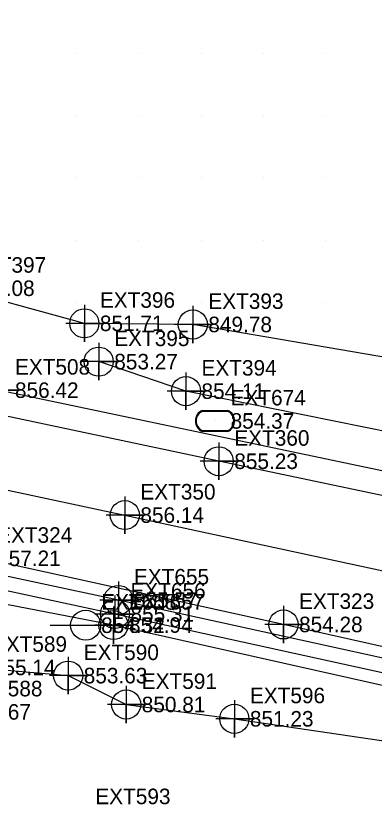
# Model space of a CAD drawing. Extents: x 1762120 to 1766775, y 709485 to 712965.
# Drawn here: x 1762750.2 to 1762807.8, y 712600.2 to 712726.1 of the extents above; entities that cross this region are included whole.
import ezdxf

# ---------------------------------------------------------------- set-up
doc = ezdxf.new("R2010")
doc.units = 0
for name, color, linetype in [('Exist DTM Breakline', 7, 'Continuous'), ('Exist DTM Breakline Cogo Elevation', 7, 'Continuous'), ('Exist DTM Breakline Cogo Number', 7, 'Continuous'), ('Exist DTM Breakline Cogo Point CELL', 7, 'Continuous'), ('Exist DTM Crownline', 7, 'Continuous'), ('Exist DTM Crownline Cogo Elevation', 7, 'Continuous'), ('Exist DTM Crownline Cogo Number', 7, 'Continuous'), ('Exist DTM Crownline Cogo Point CELL', 7, 'Continuous'), ('Exist DTM Drainline', 7, 'Continuous'), ('Exist DTM Drainline Cogo Elevation', 7, 'Continuous'), ('Exist DTM Drainline Cogo Number', 7, 'Continuous'), ('Exist DTM Drainline Cogo Point CELL', 7, 'Continuous'), ('Exist DTM QL2 LIDAR Elevation Point', 7, 'Continuous'), ('Exist Roads EOP', 7, 'Continuous'), ('Exist Roads EOP Cogo Elevation', 7, 'Continuous'), ('Exist Roads EOP Cogo Number', 7, 'Continuous'), ('Exist Roads EOP Cogo Point CELL', 7, 'Continuous'), ('Exist Utilities Gas UG Line SUE LOS C', 7, 'Continuous'), ('Exist Utilities Gas UG Line SUE LOS C Cogo Elevation', 7, 'Continuous'), ('Exist Utilities Gas UG Line SUE LOS C Cogo Number', 7, 'Continuous'), ('Exist Utilities Gas UG Line SUE LOS C Cogo Point CELL', 7, 'Continuous'), ('Exist Utilities Telephone Pole CELL', 7, 'Continuous'), ('Exist Utilities Telephone Pole Cogo Elevation', 7, 'Continuous'), ('Exist Utilities Telephone Pole Cogo Number', 7, 'Continuous'), ('Exist Utilities Telephone UG FO SUE LOS C', 7, 'Continuous'), ('Exist Utilities Telephone UG FO SUE LOS C Cogo Elevation', 7, 'Continuous'), ('Exist Utilities Telephone UG FO SUE LOS C Cogo Number', 7, 'Continuous'), ('Exist Utilities Telephone UG FO SUE LOS C Cogo Point CELL', 7, 'Continuous'), ('Exist Utilities Water Meter CELL', 7, 'Continuous'), ('Exist Utilities Water Meter Cogo Elevation', 7, 'Continuous'), ('Exist Utilities Water Meter Cogo Number', 7, 'Continuous'), ('Exist Utilities Water UG Line SUE LOS C', 7, 'Continuous'), ('Exist Utilities Water UG Line SUE LOS C Cogo Elevation', 7, 'Continuous'), ('Exist Utilities Water UG Line SUE LOS C Cogo Number', 7, 'Continuous'), ('Exist Utilities Water UG Line SUE LOS C Cogo Point CELL', 7, 'Continuous')]:
    doc.layers.add(name, color=color, linetype=linetype)

msp = doc.modelspace()

# ---------------------------------------------------------------- linework, layer by layer
at = {"layer": 'Exist DTM Breakline'}
for points in [[(1762979.15, 712640.9), (1762976.96, 712642.93), (1762967.83, 712644.52), (1762963.46, 712633.49), (1762955.46, 712627.84), (1762924.04, 712633.75), (1762890.74, 712641.89), (1762864.55, 712651.92), (1762825.23, 712656.05), (1762777.55, 712665.69), (1762763.53, 712670.44)], [(1762719.5, 712557.51), (1762723.37, 712579.21), (1762728.17, 712592.08), (1762719.69, 712602.68), (1762720.68, 712608.52), (1762728.46, 712607.7), (1762735.49, 712603.43), (1762739.91, 712614.08), (1762743.86, 712621.24), (1762758.62, 712619.92), (1762767.95, 712615.27), (1762785.33, 712612.97), (1762818.77, 712608.04), (1762844.34, 712603.2), (1762875.47, 712595.47), (1762904.98, 712592.7), (1762941.56, 712585.95), (1762969.55, 712578.67)]]:
    msp.add_lwpolyline(points, dxfattribs=at)
at = {"layer": 'Exist DTM Breakline Cogo Point CELL'}
for points in [[(1762763.53, 712673.44), (1762763.53, 712667.44), (1762763.53, 712670.44), (1762766.53, 712670.44), (1762760.53, 712670.44)], [(1762777.55, 712668.69), (1762777.55, 712662.69), (1762777.55, 712665.69), (1762780.55, 712665.69), (1762774.55, 712665.69)], [(1762758.62, 712622.92), (1762758.62, 712616.92), (1762758.62, 712619.92), (1762761.62, 712619.92), (1762755.62, 712619.92)], [(1762767.95, 712618.27), (1762767.95, 712612.27), (1762767.95, 712615.27), (1762770.95, 712615.27), (1762764.95, 712615.27)], [(1762785.33, 712615.97), (1762785.33, 712609.97), (1762785.33, 712612.97), (1762788.33, 712612.97), (1762782.33, 712612.97)]]:
    msp.add_lwpolyline(points, dxfattribs=at)
for centre in [(1762763.53, 712670.44), (1762777.55, 712665.69), (1762758.62, 712619.92), (1762767.95, 712615.27), (1762785.33, 712612.97)]:
    msp.add_circle(centre, 2.34, dxfattribs=at)
at = {"layer": 'Exist DTM Crownline'}
msp.add_lwpolyline([(1762166.55, 712774.69), (1762217.29, 712763.93), (1762266.93, 712753.16), (1762315.99, 712742.65), (1762361.3, 712733.13), (1762409.52, 712722.71), (1762461.51, 712711.51), (1762512.12, 712700.31), (1762561, 712689.86), (1762611.48, 712678.84), (1762663.77, 712667.96), (1762715.27, 712656.97), (1762767.73, 712645.75), (1762820.16, 712634.42), (1762873.56, 712623.12), (1762907.32, 712615.87), (1762954.84, 712607.61), (1762970.66, 712604.72)], dxfattribs=at)
at = {"layer": 'Exist DTM Crownline Cogo Point CELL'}
msp.add_lwpolyline([(1762767.73, 712648.75), (1762767.73, 712642.75), (1762767.73, 712645.75), (1762770.73, 712645.75), (1762764.73, 712645.75)], dxfattribs=at)
msp.add_circle((1762767.73, 712645.75), 2.34, dxfattribs=at)
at = {"layer": 'Exist DTM Drainline'}
msp.add_lwpolyline([(1762956.08, 712637.37), (1762926.01, 712644.16), (1762891.89, 712654.33), (1762866.92, 712662.34), (1762827.77, 712667.98), (1762778.65, 712676.42), (1762761.22, 712676.6), (1762740.51, 712682.25), (1762728.17, 712682.65)], dxfattribs=at)
at = {"layer": 'Exist DTM Drainline Cogo Point CELL'}
for points in [[(1762761.22, 712679.6), (1762761.22, 712673.6), (1762761.22, 712676.6), (1762764.22, 712676.6), (1762758.22, 712676.6)], [(1762778.65, 712679.42), (1762778.65, 712673.42), (1762778.65, 712676.42), (1762781.65, 712676.42), (1762775.65, 712676.42)]]:
    msp.add_lwpolyline(points, dxfattribs=at)
for centre in [(1762761.22, 712676.6), (1762778.65, 712676.42)]:
    msp.add_circle(centre, 2.34, dxfattribs=at)
at = {"layer": 'Exist DTM QL2 LIDAR Elevation Point'}
for p, q in [((1762760, 712720), (1762760, 712720)), ((1762770, 712720), (1762770, 712720)), ((1762780, 712720), (1762780, 712720)), ((1762790, 712720), (1762790, 712720)), ((1762800, 712720), (1762800, 712720)), ((1762760, 712710), (1762760, 712710)), ((1762770, 712710), (1762770, 712710)), ((1762780, 712710), (1762780, 712710)), ((1762790, 712710), (1762790, 712710)), ((1762800, 712710), (1762800, 712710)), ((1762760, 712700), (1762760, 712700)), ((1762770, 712700), (1762770, 712700)), ((1762780, 712700), (1762780, 712700)), ((1762790, 712700), (1762790, 712700)), ((1762800, 712700), (1762800, 712700)), ((1762760, 712690), (1762760, 712690)), ((1762770, 712690), (1762770, 712690)), ((1762780, 712690), (1762780, 712690)), ((1762790, 712690), (1762790, 712690)), ((1762800, 712690), (1762800, 712690)), ((1762760, 712680), (1762760, 712680)), ((1762770, 712680), (1762770, 712680)), ((1762780, 712680), (1762780, 712680)), ((1762790, 712680), (1762790, 712680)), ((1762800, 712680), (1762800, 712680))]:
    msp.add_line(p, q, dxfattribs=at)
at = {"layer": 'Exist Roads EOP'}
for points in [[(1762972.64, 712616.33), (1762930.48, 712622.91), (1762881.99, 712633.2), (1762831.97, 712644.06), (1762782.82, 712654.41), (1762735.74, 712664.41), (1762686.68, 712675.53), (1762639.56, 712685.27), (1762589.4, 712696.15), (1762546.23, 712705.49), (1762496.4, 712716.08), (1762446.15, 712726.9), (1762396.23, 712737.69), (1762346.43, 712748.23), (1762295.97, 712759.18), (1762245.1, 712770.1), (1762193.68, 712780.97), (1762169, 712786.42)], [(1762974.58, 712585.31), (1762927.98, 712597.84), (1762890.67, 712606.3), (1762842.51, 712617.09), (1762793.23, 712628.15), (1762744.7, 712638.79), (1762696.33, 712649.07), (1762645.67, 712659.58), (1762597.31, 712669.97), (1762548.88, 712680.54), (1762499.87, 712691.04), (1762451.78, 712701.31), (1762402.08, 712712.16), (1762353.64, 712722.59), (1762304.8, 712733.11), (1762255.13, 712743.65), (1762207.34, 712753.91), (1762164.28, 712763.06), (1762150.69, 712765.78)]]:
    msp.add_lwpolyline(points, dxfattribs=at)
at = {"layer": 'Exist Roads EOP Cogo Point CELL'}
for points in [[(1762782.82, 712657.41), (1762782.82, 712651.41), (1762782.82, 712654.41), (1762785.82, 712654.41), (1762779.82, 712654.41)], [(1762793.23, 712631.15), (1762793.23, 712625.15), (1762793.23, 712628.15), (1762796.23, 712628.15), (1762790.23, 712628.15)]]:
    msp.add_lwpolyline(points, dxfattribs=at)
for centre in [(1762782.82, 712654.41), (1762793.23, 712628.15)]:
    msp.add_circle(centre, 2.34, dxfattribs=at)
at = {"layer": 'Exist Utilities Gas UG Line SUE LOS C'}
msp.add_lwpolyline([(1762186.21, 712786.58), (1762241.95, 712774.53), (1762368.98, 712745.66), (1762446.66, 712730.32), (1762499.18, 712718.67), (1762560.33, 712705.06), (1762614.27, 712693.34), (1762654.57, 712685.66), (1762695.77, 712676.76), (1762747.57, 712665.85), (1762826.12, 712649.31), (1762887.98, 712636.74)], dxfattribs=at)
at = {"layer": 'Exist Utilities Gas UG Line SUE LOS C Cogo Point CELL'}
msp.add_lwpolyline([(1762747.57, 712668.85), (1762747.57, 712662.85), (1762747.57, 712665.85), (1762750.57, 712665.85), (1762744.57, 712665.85)], dxfattribs=at)
at = {"layer": 'Exist Utilities Telephone Pole CELL'}
for p, q in [((1762755.75, 712628.03), (1762767.09, 712628.03)), ((1762761.43, 712628.03), (1762761.43, 712628.03))]:
    msp.add_line(p, q, dxfattribs=at)
msp.add_circle((1762761.43, 712628.03), 2.41, dxfattribs=at)
at = {"layer": 'Exist Utilities Telephone UG FO SUE LOS C'}
for points in [[(1762975.06, 712582.94), (1762942.13, 712590.14), (1762892.88, 712602.57), (1762845.99, 712612.29), (1762766.14, 712629.83), (1762702.53, 712643.51), (1762677.77, 712648.7)], [(1762974.38, 712580.1), (1762941.96, 712587.59), (1762882.88, 712601.62), (1762847.54, 712609.71), (1762765.9, 712628.05), (1762704.22, 712639.93), (1762682.08, 712645.62)]]:
    msp.add_lwpolyline(points, dxfattribs=at)
at = {"layer": 'Exist Utilities Telephone UG FO SUE LOS C Cogo Point CELL'}
for points in [[(1762766.14, 712632.83), (1762766.14, 712626.83), (1762766.14, 712629.83), (1762769.14, 712629.83), (1762763.14, 712629.83)], [(1762765.9, 712631.05), (1762765.9, 712625.05), (1762765.9, 712628.05), (1762768.9, 712628.05), (1762762.9, 712628.05)]]:
    msp.add_lwpolyline(points, dxfattribs=at)
for centre in [(1762766.14, 712629.83), (1762765.9, 712628.05)]:
    msp.add_circle(centre, 2.34, dxfattribs=at)
at = {"layer": 'Exist Utilities Water Meter CELL'}
msp.add_line((1762782.23, 712660.89), (1762782.23, 712660.89), dxfattribs=at)
for points in [[(1762780.19, 712662.59), (1762784.27, 712662.59)], [(1762780.19, 712662.46), (1762784.27, 712662.46)], [(1762784.27, 712659.33), (1762780.17, 712659.33)], [(1762784.27, 712659.19), (1762780.17, 712659.19)]]:
    msp.add_lwpolyline(points, dxfattribs=at)
for centre, radius, start, end in [((1762780.92, 712660.89), 1.86, 113.178, 245.9794), ((1762780.93, 712660.89), 1.73, 115.3009, 243.7824), ((1762783.52, 712660.9), 1.86, 293.6483, 66.3084), ((1762783.53, 712660.89), 1.73, 295.1272, 64.8728)]:
    msp.add_arc(centre, radius, start, end, dxfattribs=at)
at = {"layer": 'Exist Utilities Water UG Line SUE LOS C'}
msp.add_lwpolyline([(1762975.81, 712587.97), (1762937.62, 712595.56), (1762895.76, 712604.03), (1762842.4, 712615.45), (1762766.69, 712632.08), (1762701.56, 712645.98), (1762676.6, 712651.12)], dxfattribs=at)
at = {"layer": 'Exist Utilities Water UG Line SUE LOS C Cogo Point CELL'}
msp.add_lwpolyline([(1762766.69, 712635.08), (1762766.69, 712629.08), (1762766.69, 712632.08), (1762769.69, 712632.08), (1762763.69, 712632.08)], dxfattribs=at)
msp.add_circle((1762766.69, 712632.08), 2.34, dxfattribs=at)

# ---------------------------------------------------------------- texts
at = {"layer": 'Exist DTM Breakline Cogo Elevation'}
for s, p in [('853.27', (1762766.03, 712669.19)), ('854.11', (1762780.05, 712664.44)), ('855.14', (1762746.36, 712619.99)), ('853.63', (1762761.12, 712618.67)), ('850.81', (1762770.45, 712614.02)), ('853.67', (1762742.41, 712612.83)), ('851.23', (1762787.83, 712611.72))]:
    msp.add_text(s, height=2.5, dxfattribs=at).set_placement(p)
at = {"layer": 'Exist DTM Breakline Cogo Number'}
for s, p in [('EXT395', (1762766.03, 712672.94)), ('EXT394', (1762780.05, 712668.19)), ('EXT589', (1762746.36, 712623.74)), ('EXT590', (1762761.12, 712622.42)), ('EXT591', (1762770.45, 712617.77)), ('EXT588', (1762742.41, 712616.58)), ('EXT596', (1762787.83, 712615.47)), ('EXT593', (1762762.99, 712599.23))]:
    msp.add_text(s, height=2.5, dxfattribs=at).set_placement(p)
at = {"layer": 'Exist DTM Crownline Cogo Elevation'}
msp.add_text('856.14', height=2.5, dxfattribs=at).set_placement((1762770.23, 712644.5))
at = {"layer": 'Exist DTM Crownline Cogo Number'}
msp.add_text('EXT350', height=2.5, dxfattribs=at).set_placement((1762770.23, 712648.25))
at = {"layer": 'Exist DTM Drainline Cogo Elevation'}
for s, p in [('854.08', (1762743.01, 712681)), ('851.71', (1762763.72, 712675.35)), ('849.78', (1762781.15, 712675.17))]:
    msp.add_text(s, height=2.5, dxfattribs=at).set_placement(p)
at = {"layer": 'Exist DTM Drainline Cogo Number'}
for s, p in [('EXT397', (1762743.01, 712684.75)), ('EXT396', (1762763.72, 712679.1)), ('EXT393', (1762781.15, 712678.92))]:
    msp.add_text(s, height=2.5, dxfattribs=at).set_placement(p)
at = {"layer": 'Exist Roads EOP Cogo Elevation'}
for s, p in [('855.23', (1762785.32, 712653.16)), ('857.21', (1762747.2, 712637.54)), ('854.28', (1762795.73, 712626.9))]:
    msp.add_text(s, height=2.5, dxfattribs=at).set_placement(p)
at = {"layer": 'Exist Roads EOP Cogo Number'}
for s, p in [('EXT360', (1762785.32, 712656.91)), ('EXT324', (1762747.2, 712641.29)), ('EXT323', (1762795.73, 712630.65))]:
    msp.add_text(s, height=2.5, dxfattribs=at).set_placement(p)
at = {"layer": 'Exist Utilities Gas UG Line SUE LOS C Cogo Elevation'}
msp.add_text('856.42', height=2.5, dxfattribs=at).set_placement((1762750.07, 712664.6))
at = {"layer": 'Exist Utilities Gas UG Line SUE LOS C Cogo Number'}
msp.add_text('EXT508', height=2.5, dxfattribs=at).set_placement((1762750.07, 712668.35))
at = {"layer": 'Exist Utilities Telephone Pole Cogo Elevation'}
msp.add_text('854.32', height=2.5, dxfattribs=at).set_placement((1762763.93, 712626.78))
at = {"layer": 'Exist Utilities Telephone Pole Cogo Number'}
msp.add_text('EXT658', height=2.5, dxfattribs=at).set_placement((1762763.93, 712630.53))
at = {"layer": 'Exist Utilities Telephone UG FO SUE LOS C Cogo Elevation'}
for s, p in [('855.31', (1762768.64, 712628.58)), ('854.94', (1762768.4, 712626.8))]:
    msp.add_text(s, height=2.5, dxfattribs=at).set_placement(p)
at = {"layer": 'Exist Utilities Telephone UG FO SUE LOS C Cogo Number'}
for s, p in [('EXT656', (1762768.64, 712632.33)), ('EXT657', (1762768.4, 712630.55))]:
    msp.add_text(s, height=2.5, dxfattribs=at).set_placement(p)
at = {"layer": 'Exist Utilities Water Meter Cogo Elevation'}
msp.add_text('854.37', height=2.5, dxfattribs=at).set_placement((1762784.73, 712659.65))
at = {"layer": 'Exist Utilities Water Meter Cogo Number'}
msp.add_text('EXT674', height=2.5, dxfattribs=at).set_placement((1762784.73, 712663.4))
at = {"layer": 'Exist Utilities Water UG Line SUE LOS C Cogo Elevation'}
msp.add_text('855.57', height=2.5, dxfattribs=at).set_placement((1762769.19, 712630.83))
at = {"layer": 'Exist Utilities Water UG Line SUE LOS C Cogo Number'}
msp.add_text('EXT655', height=2.5, dxfattribs=at).set_placement((1762769.19, 712634.58))

doc.saveas('drawing.dxf')
